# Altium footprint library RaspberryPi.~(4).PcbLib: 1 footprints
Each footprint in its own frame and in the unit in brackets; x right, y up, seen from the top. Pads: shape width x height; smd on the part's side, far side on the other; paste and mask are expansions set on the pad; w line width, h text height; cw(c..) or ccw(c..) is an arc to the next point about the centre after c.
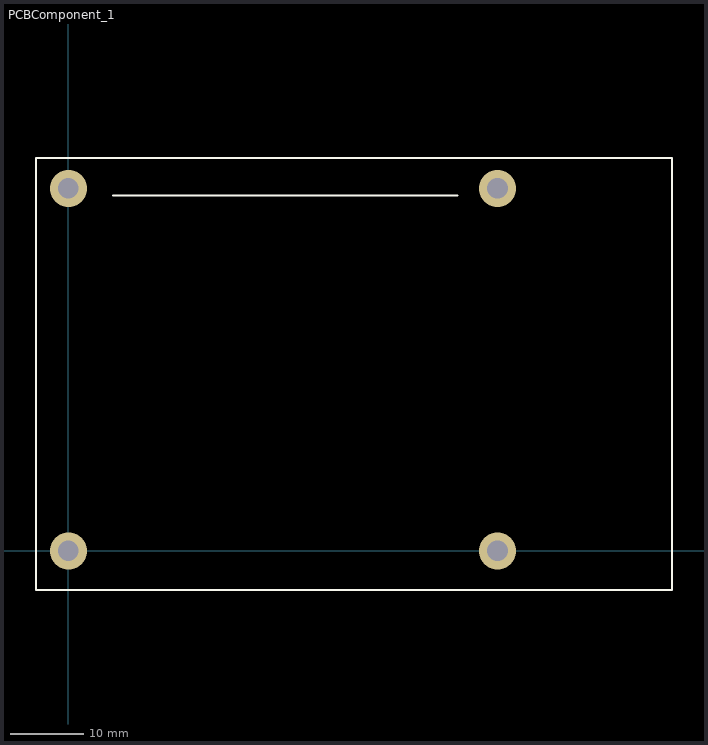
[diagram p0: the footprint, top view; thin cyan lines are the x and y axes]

## PCBComponent_1 [mm]
via -11.938,-90.932 diameter 3 hole 3
via 0,0 diameter 5 hole 2.8
via 58,0 diameter 5 hole 2.8
via 0,49 diameter 5 hole 2.8
via 58,49 diameter 5 hole 2.8
Top Overlay:
  lines w0.254: 6,48 52.6,48 ; -4.4,-5.3 81.6,-5.3 81.6,53.1 -4.4,53.1 -4.4,-5.3
3D body: height 15, standoff 0, extent 70.45,1.35 83.75,15.5
3D body: height 15, standoff 0, extent 70.55,21.75 83.85,32.25
3D body: height 15, standoff 0, extent 70.25,34.75 83.55,45.25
